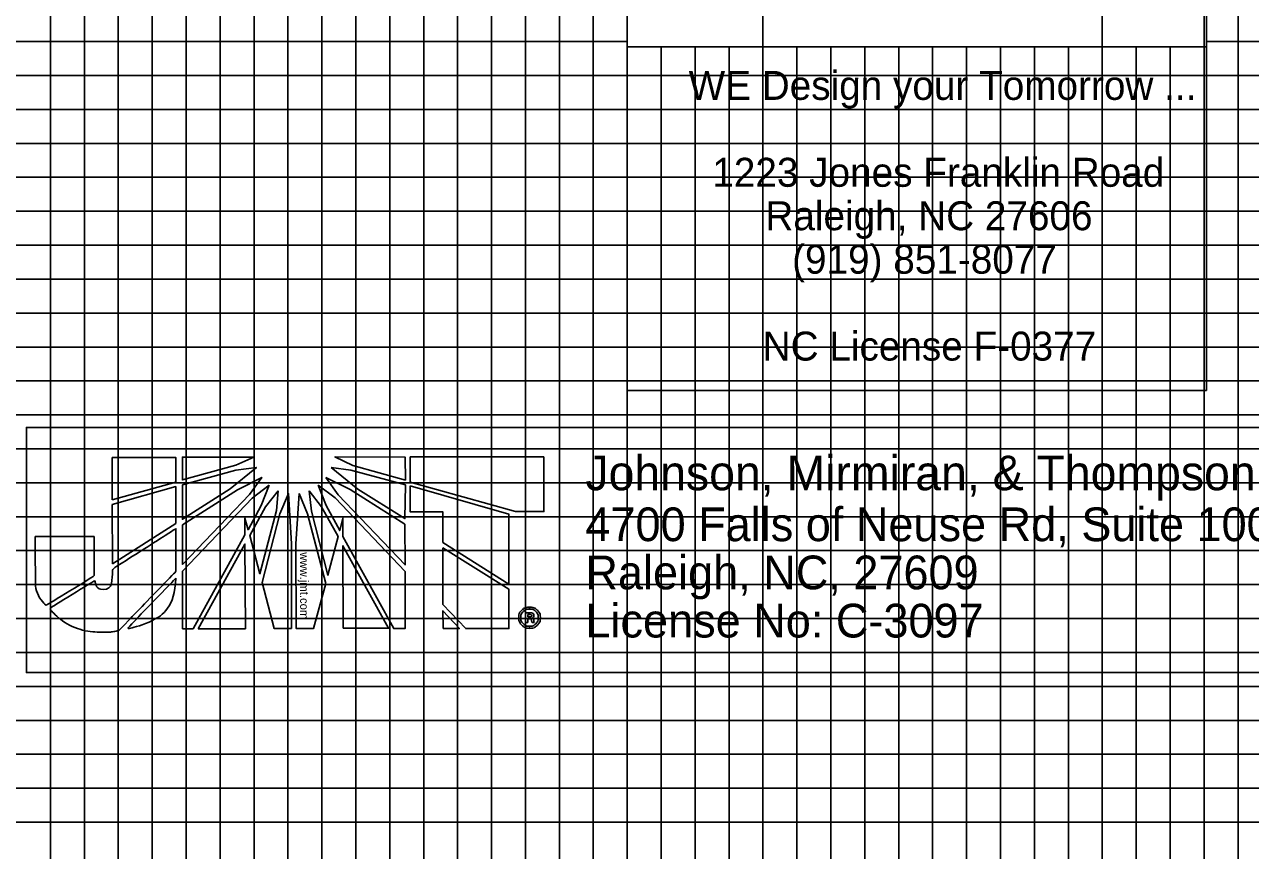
# Model space of a CAD drawing. Extents: x 557032 to 558716, y 513430 to 514605.
# Drawn here: x 558440.6 to 558621.3, y 513506.2 to 513627.9 of the extents above; entities that cross this region are included whole.
import ezdxf

# ---------------------------------------------------------------- set-up
doc = ezdxf.new("R2010")
doc.units = 0
for name, color, linetype in [('Prop DSN Text', 7, 'Continuous'), ('Prop VPI Label', 7, 'Continuous'), ('Scratch_Level_1', 7, 'Continuous'), ('Sheet DOT Grid CELL', 7, 'Continuous'), ('Sheet Profile Grid Major CELL', 7, 'Continuous'), ('Sheet Profile Grid Middle CELL', 7, 'Continuous'), ('Sheet Profile Grid Minor CELL', 7, 'Continuous')]:
    doc.layers.add(name, color=color, linetype=linetype)

msp = doc.modelspace()

# ---------------------------------------------------------------- linework, layer by layer
at = {"layer": 'Prop DSN Text'}
for p, q in [((558529.45, 513574), (558529.45, 513650.4)), ((558614.79, 513650.4), (558614.79, 513574)), ((558529.45, 513624.6), (558614.79, 513624.6)), ((558614.79, 513574), (558529.45, 513574))]:
    msp.add_line(p, q, dxfattribs=at)
at = {"layer": 'Prop VPI Label'}
for p, q in [((558462.93, 513564.13), (558453.57, 513564.12)), ((558453.57, 513564.12), (558453.57, 513557.91)), ((558462.93, 513560.51), (558462.93, 513564.13)), ((558474.44, 513564.19), (558463.9, 513564.18)), ((558463.9, 513564.18), (558463.9, 513560.82)), ((558471.75, 513562.99), (558474.44, 513564.19)), ((558496.74, 513564.16), (558486.36, 513564.2)), ((558486.36, 513564.2), (558488.99, 513562.96)), ((558496.75, 513560.79), (558496.74, 513564.16)), ((558517.15, 513564.23), (558497.47, 513564.21)), ((558497.47, 513564.21), (558497.47, 513560.59)), ((558517.16, 513556.16), (558517.15, 513564.23)), ((558463.9, 513560.82), (558471.75, 513562.99)), ((558471.75, 513562.27), (558463.9, 513560.1)), ((558470.93, 513559.49), (558474.81, 513562.64)), ((558474.81, 513562.64), (558471.75, 513562.27)), ((558485.84, 513562.65), (558489.76, 513559.44)), ((558488.73, 513562.28), (558485.84, 513562.65)), ((558496.75, 513560.08), (558488.73, 513562.28)), ((558488.99, 513562.96), (558496.75, 513560.79)), ((558453.57, 513557.91), (558462.93, 513560.51)), ((558462.93, 513559.83), (558453.57, 513557.2)), ((558462.94, 513554.41), (558462.93, 513559.83)), ((558463.9, 513560.1), (558463.91, 513555.03)), ((558475.58, 513561.19), (558472.01, 513559.38)), ((558473.78, 513558.65), (558475.58, 513561.19)), ((558476.66, 513560.06), (558474.18, 513558.15)), ((558475.52, 513557.07), (558476.66, 513560.06)), ((558483.92, 513560.07), (558485.07, 513557.07)), ((558486.41, 513558.16), (558483.92, 513560.07)), ((558485.02, 513561.2), (558486.83, 513558.62)), ((558488.64, 513559.39), (558485.02, 513561.2)), ((558496.69, 513555.12), (558496.75, 513560.08)), ((558497.47, 513560.59), (558497.47, 513560.48)), ((558497.47, 513560.48), (558512.97, 513556.16)), ((558497.47, 513559.93), (558497.47, 513559.87)), ((558511.98, 513555.8), (558497.47, 513559.93)), ((558497.47, 513559.87), (558497.48, 513556.1)), ((558463.91, 513555.03), (558470.93, 513559.49)), ((558472.01, 513559.38), (558463.91, 513554.21)), ((558463.92, 513548.37), (558473.78, 513558.65)), ((558474.18, 513558.15), (558463.92, 513547.38)), ((558478.01, 513559.23), (558476.16, 513556.85)), ((558477.75, 513556.34), (558478.01, 513559.23)), ((558479.55, 513558.81), (558478.27, 513555.82)), ((558479.96, 513551.43), (558479.55, 513558.81)), ((558481.1, 513558.82), (558480.63, 513551.43)), ((558482.34, 513555.82), (558481.1, 513558.82)), ((558482.6, 513559.23), (558482.91, 513556.24)), ((558484.41, 513556.86), (558482.6, 513559.23)), ((558496.7, 513547.32), (558486.41, 513558.16)), ((558486.83, 513558.62), (558496.7, 513548.3)), ((558496.69, 513554.29), (558488.64, 513559.39)), ((558489.76, 513559.44), (558496.69, 513555.12)), ((558453.57, 513557.2), (558453.58, 513548.47)), ((558473.57, 513553.49), (558475.52, 513557.07)), ((558476.16, 513556.85), (558473.83, 513552.61)), ((558475.33, 513546.99), (558477.75, 513556.34)), ((558482.91, 513556.24), (558485.34, 513546.79)), ((558486.84, 513552.47), (558484.41, 513556.86)), ((558485.07, 513557.07), (558487.08, 513553.35)), ((558497.48, 513556.1), (558502.28, 513556.1)), ((558502.28, 513556.1), (558502.28, 513551.61)), ((558512.97, 513556.16), (558517.16, 513556.16)), ((558453.58, 513548.47), (558462.94, 513554.41)), ((558473.1, 513552.72), (558473.1, 513555.19)), ((558473.1, 513555.19), (558473.57, 513553.49)), ((558478.27, 513555.82), (558475.64, 513545.7)), ((558485.03, 513545.55), (558482.34, 513555.82)), ((558487.08, 513553.35), (558487.56, 513555.21)), ((558487.56, 513555.21), (558487.56, 513552.47)), ((558496.7, 513548.3), (558496.69, 513554.29)), ((558511.99, 513545.47), (558511.98, 513555.8)), ((558463.91, 513554.21), (558463.92, 513548.37)), ((558465.47, 513538.89), (558473.1, 513552.72)), ((558473.83, 513552.61), (558475.33, 513546.99)), ((558473.1, 513551.38), (558466.2, 513538.89)), ((558473.18, 513538.9), (558473.1, 513551.38)), ((558479.97, 513538.95), (558479.96, 513551.43)), ((558480.63, 513551.43), (558480.64, 513538.95)), ((558485.34, 513546.79), (558486.84, 513552.47)), ((558487.56, 513552.47), (558495.05, 513538.92)), ((558494.28, 513538.96), (558487.56, 513551.13)), ((558487.56, 513551.13), (558487.57, 513538.96)), ((558502.28, 513551.61), (558511.99, 513545.47)), ((558502.28, 513550.83), (558502.29, 513542.46)), ((558511.99, 513544.74), (558502.28, 513550.83)), ((558463.92, 513547.38), (558463.92, 513538.89)), ((558496.7, 513538.92), (558496.7, 513547.32)), ((558475.64, 513545.7), (558477.41, 513538.95)), ((558483.23, 513538.95), (558485.03, 513545.55)), ((558512, 513538.93), (558511.99, 513544.74)), ((558502.29, 513542.46), (558505.65, 513538.93)), ((558515.04, 513542.1), (558515.04, 513541.8)), ((558515.04, 513541.8), (558515.04, 513542.1)), ((558504.72, 513538.93), (558502.29, 513541.55)), ((558502.29, 513541.55), (558502.3, 513538.92)), ((558514.46, 513539.82), (558514.46, 513541.25)), ((558514.46, 513541.25), (558515.05, 513541.25)), ((558515.05, 513540.98), (558514.79, 513540.98)), ((558514.79, 513540.98), (558514.79, 513540.64)), ((558514.79, 513540.64), (558515.05, 513540.64)), ((558515.05, 513540.38), (558514.79, 513540.38)), ((558514.79, 513540.38), (558514.79, 513539.82)), ((558515.05, 513541.25), (558515.05, 513540.98)), ((558515.05, 513540.98), (558515.05, 513541.25)), ((558515.05, 513541.25), (558515.14, 513541.25)), ((558515.08, 513540.98), (558515.05, 513540.98)), ((558515.05, 513540.64), (558515.05, 513540.38)), ((558515.05, 513540.38), (558515.05, 513540.64)), ((558515.05, 513540.64), (558515.06, 513540.64)), ((558515.06, 513540.38), (558515.05, 513540.38)), ((558463.92, 513538.89), (558465.47, 513538.89)), ((558466.2, 513538.89), (558473.18, 513538.9)), ((558477.41, 513538.95), (558479.97, 513538.95)), ((558480.64, 513538.95), (558483.23, 513538.95)), ((558487.57, 513538.96), (558494.28, 513538.96)), ((558495.05, 513538.92), (558496.7, 513538.92)), ((558502.3, 513538.92), (558504.72, 513538.93)), ((558505.65, 513538.93), (558512, 513538.93)), ((558514.79, 513539.82), (558514.46, 513539.82)), ((558515.05, 513539.26), (558515.05, 513538.95)), ((558515.05, 513538.95), (558515.05, 513539.26)), ((558515.05, 513539.26), (558515.06, 513539.26)), ((558515.06, 513538.95), (558515.05, 513538.95))]:
    msp.add_line(p, q, dxfattribs=at)
for points in [[(558529.45, 513624.6), (558614.79, 513624.6), (558614.79, 513574), (558529.45, 513574)], [(558440.91, 513568.55), (558640.94, 513568.55), (558640.94, 513532.45), (558440.91, 513532.45)], [(558440.91, 513532.45), (558640.94, 513532.45), (558640.94, 513568.55), (558440.91, 513568.55)]]:
    msp.add_lwpolyline(points, close=True, dxfattribs=at)
for points in [[(558453.57, 513557.91), (558462.93, 513560.51), (558462.93, 513564.13), (558453.57, 513564.12), (558453.57, 513557.91)], [(558471.75, 513562.99), (558474.44, 513564.19), (558463.9, 513564.18), (558463.9, 513560.82), (558471.75, 513562.99)], [(558488.99, 513562.96), (558496.75, 513560.79), (558496.74, 513564.16), (558486.36, 513564.2), (558488.99, 513562.96)], [(558517.15, 513564.23), (558497.47, 513564.21), (558497.47, 513560.59), (558497.47, 513560.48), (558512.97, 513556.16), (558517.16, 513556.16), (558517.15, 513564.23)], [(558463.9, 513560.1), (558463.91, 513555.03), (558470.93, 513559.49), (558474.81, 513562.64), (558471.75, 513562.27), (558463.9, 513560.1)], [(558485.84, 513562.65), (558489.76, 513559.44), (558496.69, 513555.12), (558496.75, 513560.08), (558488.73, 513562.28), (558485.84, 513562.65)], [(558453.58, 513548.47), (558462.94, 513554.41), (558462.93, 513559.83), (558453.57, 513557.2), (558453.58, 513548.47)], [(558463.91, 513554.21), (558463.92, 513548.37), (558473.78, 513558.65), (558475.58, 513561.19), (558472.01, 513559.38), (558463.91, 513554.21)], [(558476.66, 513560.06), (558474.18, 513558.15), (558463.92, 513547.38), (558463.92, 513538.89), (558465.47, 513538.89), (558473.1, 513552.72), (558473.1, 513555.19), (558473.57, 513553.49), (558475.52, 513557.07), (558476.66, 513560.06)], [(558483.92, 513560.07), (558485.07, 513557.07), (558487.08, 513553.35), (558487.56, 513555.21), (558487.56, 513552.47), (558495.05, 513538.92), (558496.7, 513538.92), (558496.7, 513547.32), (558486.41, 513558.16), (558483.92, 513560.07)], [(558485.02, 513561.2), (558486.83, 513558.62), (558496.7, 513548.3), (558496.69, 513554.29), (558488.64, 513559.39), (558485.02, 513561.2)], [(558497.47, 513559.93), (558497.47, 513559.87), (558497.48, 513556.1), (558502.28, 513556.1), (558502.28, 513551.61), (558511.99, 513545.47), (558511.98, 513555.8), (558497.47, 513559.93)], [(558478.01, 513559.23), (558476.16, 513556.85), (558473.83, 513552.61), (558475.33, 513546.99), (558477.75, 513556.34), (558478.01, 513559.23)], [(558478.27, 513555.82), (558475.64, 513545.7), (558477.41, 513538.95), (558479.97, 513538.95), (558479.96, 513551.43), (558479.55, 513558.81), (558478.27, 513555.82)], [(558481.1, 513558.82), (558480.63, 513551.43), (558480.64, 513538.95), (558483.23, 513538.95), (558485.03, 513545.55), (558482.34, 513555.82), (558481.1, 513558.82)], [(558482.6, 513559.23), (558482.91, 513556.24), (558485.34, 513546.79), (558486.84, 513552.47), (558484.41, 513556.86), (558482.6, 513559.23)], [(558466.2, 513538.89), (558473.18, 513538.9), (558473.1, 513551.38), (558466.2, 513538.89)], [(558487.57, 513538.96), (558494.28, 513538.96), (558487.56, 513551.13), (558487.57, 513538.96)], [(558502.28, 513550.83), (558502.29, 513542.46), (558505.65, 513538.93), (558512, 513538.93), (558511.99, 513544.74), (558502.28, 513550.83), (558502.28, 513550.83)], [(558502.3, 513538.92), (558502.3, 513538.92), (558504.72, 513538.93), (558502.29, 513541.55), (558502.3, 513538.92)], [(558515.67, 513540.16), (558515.67, 513540.08), (558515.68, 513540.03), (558515.68, 513539.98), (558515.72, 513539.82), (558515.42, 513539.82)]]:
    msp.add_lwpolyline(points, dxfattribs=at)
for points, degree in [([(558450.89, 513552.48), (558450.89, 513552.48), (558442.22, 513552.48), (558442.22, 513552.48), (558442.22, 513552.48), (558442.23, 513547.05), (558442.23, 513547.05), (558442.23, 513547.05), (558442.23, 513546.48), (558442.23, 513546.48), (558442.23, 513544.78), (558442.79, 513543.44), (558443.78, 513542.31), (558443.78, 513542.31), (558450.89, 513546.65), (558450.89, 513546.75), (558450.89, 513546.75), (558450.89, 513552.48), (558450.89, 513552.48)], 3), ([(558452.24, 513544.68), (558451.68, 513544.68), (558451.21, 513544.99), (558451, 513546.03), (558451, 513546.03), (558444.29, 513541.87), (558444.29, 513541.87), (558446.36, 513539.69), (558449.67, 513538.4), (558452.46, 513538.4), (558453.19, 513538.4), (558453.74, 513538.46), (558454.52, 513538.62), (558454.52, 513538.62), (558462.94, 513547.34), (558462.94, 513547.34), (558462.94, 513547.34), (558462.94, 513553.64), (558462.94, 513553.64), (558462.94, 513553.64), (558453.58, 513547.68), (558453.58, 513547.68), (558453.58, 513545.32), (558453.01, 513544.69), (558452.24, 513544.68)], 3), ([(558452.24, 513544.68), (558451.68, 513544.68), (558451.21, 513544.99), (558451, 513546.03), (558451, 513546.03), (558444.29, 513541.87), (558444.29, 513541.87), (558446.36, 513539.69), (558449.67, 513538.4), (558452.46, 513538.4), (558453.19, 513538.4), (558453.74, 513538.46), (558454.52, 513538.62), (558454.52, 513538.62), (558462.94, 513547.34), (558462.94, 513547.34), (558462.94, 513547.34), (558462.94, 513553.64), (558462.94, 513553.64), (558462.94, 513553.64), (558453.58, 513547.68), (558453.58, 513547.68), (558453.58, 513545.32), (558453.01, 513544.69), (558452.24, 513544.68)], 3), ([(558462.94, 513546.35), (558462.94, 513546.35), (558455.66, 513538.82), (558455.66, 513538.82), (558459.23, 513539.7), (558462.78, 513542.07), (558462.94, 513546.35)], 3), ([(558515.05, 513538.95), (558514.62, 513538.95), (558514.24, 513539.1), (558513.93, 513539.42), (558513.62, 513539.71), (558513.46, 513540.09), (558513.46, 513540.53), (558513.46, 513540.98), (558513.61, 513541.35), (558513.93, 513541.64), (558514.24, 513541.94), (558514.6, 513542.1), (558515.04, 513542.1)], 3), ([(558515.04, 513541.8), (558514.69, 513541.8), (558514.39, 513541.68), (558514.15, 513541.45), (558513.9, 513541.2), (558513.77, 513540.89), (558513.77, 513540.53), (558513.77, 513540.18), (558513.9, 513539.87), (558514.15, 513539.62), (558514.4, 513539.38), (558514.7, 513539.26), (558515.05, 513539.26)], 3), ([(558515.04, 513542.1), (558515.49, 513542.1), (558515.86, 513541.94), (558516.18, 513541.64), (558516.49, 513541.36), (558516.65, 513540.98), (558516.65, 513540.54)], 3), ([(558515.06, 513539.26), (558515.41, 513539.26), (558515.71, 513539.38), (558515.96, 513539.63), (558516.2, 513539.87), (558516.33, 513540.19), (558516.33, 513540.54), (558516.33, 513540.89), (558516.2, 513541.2), (558515.96, 513541.45), (558515.71, 513541.68), (558515.41, 513541.8), (558515.04, 513541.8)], 3), ([(558515.06, 513540.64), (558515.27, 513540.64), (558515.37, 513540.7), (558515.37, 513540.82), (558515.37, 513540.93), (558515.28, 513540.98), (558515.08, 513540.98)], 3), ([(558516.65, 513540.54), (558516.65, 513540.09), (558516.49, 513539.72), (558516.19, 513539.41), (558515.88, 513539.11), (558515.5, 513538.95), (558515.06, 513538.95)], 3), ([(558515.31, 513540.33), (558515.27, 513540.35), (558515.19, 513540.38), (558515.06, 513540.38)], 2), ([(558515.14, 513541.25), (558515.5, 513541.25), (558515.68, 513541.11), (558515.68, 513540.82), (558515.68, 513540.69), (558515.63, 513540.59), (558515.51, 513540.51)], 3), ([(558515.42, 513539.82), (558515.39, 513539.9), (558515.36, 513539.98), (558515.36, 513540.08), (558515.36, 513540.21), (558515.35, 513540.29), (558515.31, 513540.33)], 3), ([(558515.51, 513540.51), (558515.61, 513540.46), (558515.66, 513540.34), (558515.67, 513540.16)], 2)]:
    msp.add_open_spline(points, degree=degree, dxfattribs=at)
at = {"layer": 'Scratch_Level_1'}
msp.add_line((558549.45, 513507.59), (558549.45, 513799.35), dxfattribs=at)
at = {"layer": 'Sheet DOT Grid CELL'}
for p, q in [((558449.45, 513980.4), (558449.45, 513480.4)), ((558499.45, 513980.4), (558499.45, 513480.4)), ((558549.45, 513980.4), (558549.45, 513480.4)), ((558599.45, 513980.4), (558599.45, 513480.4)), ((558449.45, 513953.77), (558449.45, 513504.34)), ((558499.45, 513953.77), (558499.45, 513507.95)), ((558549.45, 513953.77), (558549.45, 513507.59)), ((558599.45, 513953.77), (558599.45, 513507.22)), ((557199.45, 513580.4), (558699.34, 513580.4)), ((557202.73, 513580.4), (558694.65, 513580.4)), ((557199.45, 513530.4), (558699.34, 513530.4)), ((557202.31, 513530.4), (558694.93, 513530.4))]:
    msp.add_line(p, q, dxfattribs=at)
at = {"layer": 'Sheet Profile Grid Major CELL'}
for points in [[(558399.45, 513980.4), (558449.45, 513980.4), (558449.45, 513480.4), (558499.45, 513480.4), (558499.45, 513980.4), (558549.45, 513980.4), (558549.45, 513650.4)], [(558449.45, 513953.77), (558449.45, 513504.34)], [(558499.45, 513507.95), (558499.45, 513953.77)], [(558549.45, 513624.6), (558549.45, 513480.4), (558599.45, 513480.4), (558599.45, 513480.4), (558599.45, 513624.6)], [(558549.45, 513624.6), (558549.45, 513507.59)], [(558599.45, 513507.22), (558599.45, 513624.6)], [(558699.45, 513580.4), (557199.45, 513580.4), (557199.45, 513580.4), (557199.45, 513530.4), (558699.45, 513530.4)], [(558694.65, 513580.4), (557202.73, 513580.4)], [(557202.31, 513530.4), (558694.93, 513530.4)]]:
    msp.add_lwpolyline(points, dxfattribs=at)
at = {"layer": 'Sheet Profile Grid Middle CELL'}
for points in [[(558424.45, 513980.4), (558474.45, 513980.4), (558474.45, 513480.4), (558524.45, 513480.4), (558524.45, 513980.4), (558574.45, 513980.4), (558574.45, 513650.4)], [(558574.45, 513624.6), (558574.45, 513480.4), (558624.45, 513480.4), (558624.45, 513980.4)], [(558474.45, 513953.77), (558474.45, 513508.13)], [(558524.45, 513507.77), (558524.45, 513953.77)], [(558574.45, 513624.6), (558574.45, 513507.4)], [(558699.45, 513605.4), (557199.45, 513605.4), (557199.45, 513555.4), (558699.45, 513555.4)], [(558694.51, 513605.4), (557202.94, 513605.4)], [(557202.52, 513555.4), (558694.79, 513555.4)]]:
    msp.add_lwpolyline(points, dxfattribs=at)
at = {"layer": 'Sheet Profile Grid Minor CELL'}
for p, q in [((557249.45, 513625.4), (558529.45, 513625.4)), ((557249.45, 513625.4), (558529.45, 513625.4)), ((558614.79, 513625.4), (558649.45, 513625.4)), ((558614.79, 513625.4), (558649.45, 513625.4)), ((558649.45, 513620.4), (557249.45, 513620.4)), ((558649.45, 513620.4), (557249.45, 513620.4)), ((557249.45, 513615.4), (558649.45, 513615.4)), ((557249.45, 513615.4), (558649.45, 513615.4)), ((558649.45, 513610.4), (557249.45, 513610.4)), ((558649.45, 513610.4), (557249.45, 513610.4)), ((557249.45, 513600.4), (558649.45, 513600.4)), ((557249.45, 513600.4), (558649.45, 513600.4)), ((558649.45, 513595.4), (557249.45, 513595.4)), ((558649.45, 513595.4), (557249.45, 513595.4)), ((557249.45, 513590.4), (558649.45, 513590.4)), ((557249.45, 513590.4), (558649.45, 513590.4)), ((558649.45, 513585.4), (557249.45, 513585.4)), ((558649.45, 513585.4), (557249.45, 513585.4)), ((557249.45, 513575.4), (558649.45, 513575.4)), ((557249.45, 513575.4), (558649.45, 513575.4)), ((558649.45, 513570.4), (557249.45, 513570.4)), ((558649.45, 513570.4), (557249.45, 513570.4)), ((557249.45, 513565.4), (558649.45, 513565.4)), ((557249.45, 513565.4), (558649.45, 513565.4)), ((558649.45, 513560.4), (557249.45, 513560.4)), ((558649.45, 513560.4), (557249.45, 513560.4)), ((557249.45, 513550.4), (558649.45, 513550.4)), ((557249.45, 513550.4), (558649.45, 513550.4)), ((558649.45, 513545.4), (557249.45, 513545.4)), ((558649.45, 513545.4), (557249.45, 513545.4)), ((557249.45, 513540.4), (558649.45, 513540.4)), ((557249.45, 513540.4), (558649.45, 513540.4)), ((558649.45, 513535.4), (557249.45, 513535.4)), ((558649.45, 513535.4), (557249.45, 513535.4)), ((557249.45, 513525.4), (558649.45, 513525.4)), ((557249.45, 513525.4), (558649.45, 513525.4)), ((558649.45, 513520.4), (557249.45, 513520.4)), ((558649.45, 513520.4), (557249.45, 513520.4)), ((557249.45, 513515.4), (558649.45, 513515.4)), ((557249.45, 513515.4), (558649.45, 513515.4)), ((558649.45, 513510.4), (557249.45, 513510.4)), ((558649.45, 513510.4), (557249.45, 513510.4))]:
    msp.add_line(p, q, dxfattribs=at)
for points in [[(558439.45, 513480.4), (558444.45, 513480.4), (558444.45, 513980.4)], [(558454.45, 513980.4), (558454.45, 513480.4), (558459.45, 513480.4), (558459.45, 513980.4)], [(558464.45, 513980.4), (558464.45, 513480.4), (558469.45, 513480.4), (558469.45, 513980.4)], [(558479.45, 513980.4), (558479.45, 513480.4), (558484.45, 513480.4), (558484.45, 513980.4)], [(558489.45, 513980.4), (558489.45, 513480.4), (558494.45, 513480.4), (558494.45, 513980.4)], [(558504.45, 513980.4), (558504.45, 513480.4), (558509.45, 513480.4), (558509.45, 513980.4)], [(558514.45, 513980.4), (558514.45, 513480.4), (558519.45, 513480.4), (558519.45, 513980.4)], [(558529.45, 513980.4), (558529.45, 513480.4), (558534.45, 513480.4), (558534.45, 513624.6)], [(558609.45, 513650.4), (558609.45, 513980.4), (558614.45, 513980.4), (558614.45, 513480.4), (558619.45, 513480.4), (558619.45, 513980.4), (558629.45, 513980.4), (558629.45, 513480.4), (558634.45, 513480.4), (558634.45, 513980.4), (558639.45, 513980.4), (558639.45, 513480.4), (558644.45, 513480.4), (558644.45, 513980.4), (558649.45, 513980.4)], [(558444.45, 513496.67), (558444.45, 513953.77)], [(558454.45, 513953.77), (558454.45, 513508.28)], [(558459.45, 513508.24), (558459.45, 513953.77)], [(558464.45, 513953.77), (558464.45, 513508.21)], [(558469.45, 513508.17), (558469.45, 513953.77)], [(558479.45, 513953.77), (558479.45, 513508.1)], [(558484.45, 513508.06), (558484.45, 513953.77)], [(558489.45, 513953.77), (558489.45, 513508.02)], [(558494.45, 513507.99), (558494.45, 513953.77)], [(558504.45, 513953.77), (558504.45, 513507.92)], [(558509.45, 513507.88), (558509.45, 513953.77)], [(558514.45, 513953.77), (558514.45, 513507.84)], [(558519.45, 513507.81), (558519.45, 513953.77)], [(558529.45, 513953.77), (558529.45, 513507.73)], [(558614.45, 513953.77), (558614.45, 513507.11)], [(558619.45, 513507.08), (558619.45, 513953.77)], [(558534.45, 513507.7), (558534.45, 513624.6)], [(558539.45, 513624.6), (558539.45, 513480.4), (558544.45, 513480.4), (558544.45, 513624.6)], [(558539.45, 513624.6), (558539.45, 513507.66)], [(558544.45, 513507.62), (558544.45, 513624.6)], [(558554.45, 513624.6), (558554.45, 513480.4), (558559.45, 513480.4), (558559.45, 513624.6)], [(558554.45, 513624.6), (558554.45, 513507.55)], [(558559.45, 513507.51), (558559.45, 513624.6)], [(558564.45, 513624.6), (558564.45, 513480.4), (558569.45, 513480.4), (558569.45, 513624.6)], [(558564.45, 513624.6), (558564.45, 513507.48)], [(558569.45, 513507.44), (558569.45, 513624.6)], [(558579.45, 513624.6), (558579.45, 513480.4), (558584.45, 513480.4), (558584.45, 513624.6)], [(558579.45, 513624.6), (558579.45, 513507.37)], [(558584.45, 513507.33), (558584.45, 513624.6)], [(558589.45, 513624.6), (558589.45, 513480.4), (558594.45, 513480.4), (558594.45, 513624.6)], [(558589.45, 513624.6), (558589.45, 513507.3)], [(558594.45, 513507.26), (558594.45, 513624.6)], [(558604.45, 513624.6), (558604.45, 513480.4), (558609.45, 513480.4), (558609.45, 513624.6)], [(558604.45, 513624.6), (558604.45, 513507.19)], [(558609.45, 513507.15), (558609.45, 513624.6)]]:
    msp.add_lwpolyline(points, dxfattribs=at)

# ---------------------------------------------------------------- texts
at = {"layer": 'Prop DSN Text'}
for s, p in [('WE Design your Tomorrow ...', (558538.49, 513616.8)), ('1223 Jones Franklin Road', (558541.98, 513604)), ('Raleigh, NC 27606', (558549.8, 513597.6)), ('(919) 851-8077', (558553.74, 513591.2)), ('NC License F-0377', (558549.4, 513578.4))]:
    msp.add_text(s, height=4.2667, rotation=0, dxfattribs=at).set_placement(p)
at = {"layer": 'Prop VPI Label'}
for s, height, p in [('Johnson, Mirmiran, & Thompson Inc.', 5.1112, (558523.28, 513559.3)), ('4700 Falls of Neuse Rd, Suite 100, ', 4.9652, (558523.28, 513551.8)), ('Raleigh, NC, 27609', 4.9652, (558523.28, 513544.71)), ('License No: C-3097', 4.9652, (558523.28, 513537.61))]:
    msp.add_text(s, height=height, dxfattribs=at).set_placement(p)
msp.add_text('www.jmt.com', height=1.2413, rotation=270, dxfattribs=at).set_placement((558481.25, 513550.16))

doc.saveas('drawing.dxf')
